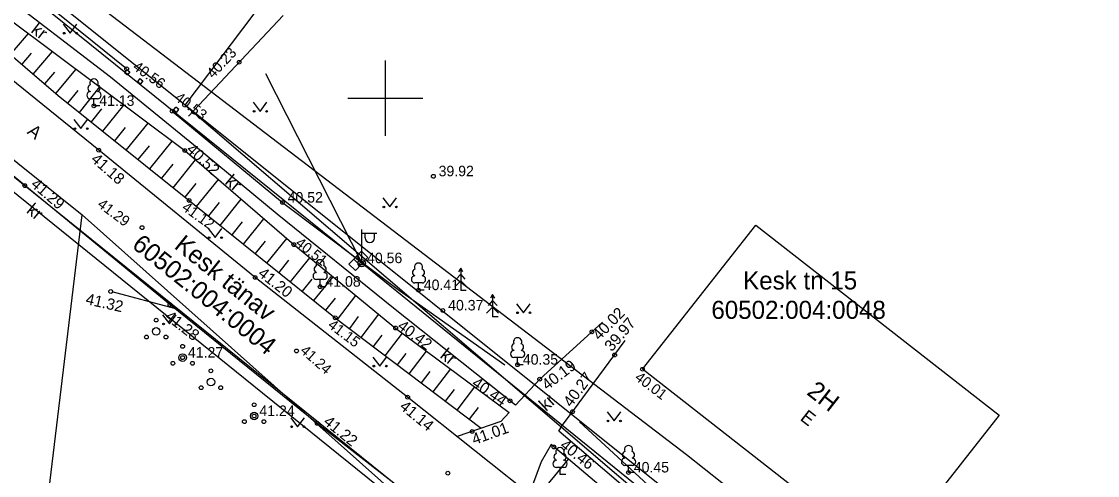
# Model space of a CAD drawing. Extents: x 641898 to 642452, y 6471715 to 6472255.
# Drawn here: x 642175.8 to 642247.4, y 6471924.9 to 6471955.1 of the extents above; entities that cross this region are included whole.
import ezdxf

# ---------------------------------------------------------------- set-up
doc = ezdxf.new("R2010")
doc.units = 0
for name, color, linetype in [('AED', 7, 'Continuous'), ('ELRAJATISMP', 7, 'Continuous'), ('HALJASTUS', 7, 'Continuous'), ('HOONE', 7, 'Continuous'), ('KORGUS-EH2000', 7, 'Continuous'), ('KTRASS', 7, 'Continuous'), ('MPOHULIIN', 7, 'Continuous'), ('PIIR', 7, 'Continuous'), ('POST', 7, 'Continuous'), ('PUU', 7, 'Continuous'), ('RELJEEF', 7, 'Continuous'), ('TEE', 7, 'Continuous'), ('VORK', 7, 'Continuous'), ('VTRASS', 7, 'Continuous')]:
    doc.layers.add(name, color=color, linetype=linetype)

msp = doc.modelspace()

# ---------------------------------------------------------------- linework, layer by layer
at = {"layer": 'AED'}
for p, q in [((642182.804, 6471951.902), (642182.661, 6471951.697)), ((642182.804, 6471951.902), (642183.009, 6471951.759)), ((642182.661, 6471951.697), (642182.866, 6471951.554)), ((642183.009, 6471951.759), (642182.866, 6471951.554)), ((642183.67, 6471951.306), (642183.514, 6471951.11)), ((642183.514, 6471951.11), (642183.71, 6471950.954)), ((642183.67, 6471951.306), (642183.866, 6471951.15)), ((642183.866, 6471951.15), (642183.71, 6471950.954)), ((642185.91, 6471949.205), (642186.066, 6471949.401)), ((642186.106, 6471949.049), (642185.91, 6471949.205)), ((642186.262, 6471949.245), (642186.066, 6471949.401)), ((642186.106, 6471949.049), (642186.262, 6471949.245))]:
    msp.add_line(p, q, dxfattribs=at)
at = {"layer": 'ELRAJATISMP'}
for p, q in [((642198.413, 6471939.812), (642197.582, 6471938.953)), ((642198.842, 6471939.397), (642198.413, 6471939.812)), ((642197.582, 6471938.953), (642198.011, 6471938.538)), ((642197.903, 6471939.285), (642198.332, 6471938.87)), ((642198.011, 6471938.538), (642198.842, 6471939.397)), ((642198.092, 6471939.48), (642198.521, 6471939.065))]:
    msp.add_line(p, q, dxfattribs=at)
at = {"layer": 'HALJASTUS'}
for p, q in [((642178.587, 6471954.924), (642179.05, 6471954.317)), ((642179.05, 6471954.317), (642179.496, 6471954.924)), ((642191.213, 6471949.724), (642191.677, 6471949.117)), ((642191.677, 6471949.117), (642192.122, 6471949.724)), ((642179.291, 6471948.578), (642179.755, 6471947.971)), ((642179.755, 6471947.971), (642180.2, 6471948.578)), ((642199.842, 6471943.362), (642200.306, 6471942.756)), ((642200.306, 6471942.756), (642200.751, 6471943.362)), ((642188.218, 6471941.32), (642188.682, 6471940.714)), ((642188.682, 6471940.714), (642189.127, 6471941.32)), ((642208.732, 6471936.318), (642209.196, 6471935.711)), ((642209.196, 6471935.711), (642209.641, 6471936.318)), ((642185.191, 6471935.578), (642185.655, 6471934.972)), ((642185.655, 6471934.972), (642186.1, 6471935.578)), ((642199.174, 6471932.77), (642199.638, 6471932.163)), ((642199.638, 6471932.163), (642200.083, 6471932.77)), ((642214.745, 6471929.119), (642215.208, 6471928.513)), ((642215.208, 6471928.513), (642215.654, 6471929.119)), ((642193.707, 6471928.732), (642194.17, 6471928.126)), ((642194.17, 6471928.126), (642194.616, 6471928.732))]:
    msp.add_line(p, q, dxfattribs=at)
for points in [[(642182.798, 6471951.948), (642174.449, 6471958.694), (642170.419, 6471961.008)], [(642186.905, 6471948.809), (642193.214, 6471955.496)], [(642185.82, 6471949.131), (642193.157, 6471943.048), (642200.95, 6471937.2), (642207.952, 6471932.258)], [(642212.922, 6471928.455), (642221.728, 6471920.311), (642230.423, 6471913.829), (642238.86, 6471907.776), (642246.219, 6471901.994)]]:
    msp.add_lwpolyline(points, dxfattribs=at)
for centre in [(642178.649, 6471954.317), (642179.478, 6471954.317), (642191.276, 6471949.117), (642192.105, 6471949.117), (642179.354, 6471947.971), (642180.183, 6471947.971), (642199.905, 6471942.756), (642200.734, 6471942.756), (642188.281, 6471940.714), (642189.109, 6471940.714), (642208.795, 6471935.711), (642209.624, 6471935.711), (642185.254, 6471934.972), (642186.082, 6471934.972), (642199.237, 6471932.163), (642200.065, 6471932.163), (642214.807, 6471928.513), (642215.636, 6471928.513), (642193.769, 6471928.126), (642194.598, 6471928.126)]:
    msp.add_circle(centre, 0.055, dxfattribs=at)
at = {"layer": 'HOONE'}
msp.add_lwpolyline([(642240.821, 6471928.89), (642233.287, 6471919.295), (642217.105, 6471931.958), (642224.638, 6471941.553), (642240.821, 6471928.89)], dxfattribs=at)
at = {"layer": 'KORGUS-EH2000'}
for centre in [(642182.798, 6471951.948), (642190.28, 6471952.386), (642180.626, 6471949.484), (642185.82, 6471949.131), (642180.941, 6471946.534), (642186.663, 6471946.509), (642203.195, 6471944.797), (642176.022, 6471944.175), (642186.952, 6471943.184), (642193.157, 6471943.048), (642183.82, 6471941.38), (642193.917, 6471940.248), (642198.436, 6471939.015), (642191.341, 6471938.065), (642195.668, 6471937.448), (642181.74, 6471937.129), (642202.208, 6471937.223), (642185.674, 6471936.257), (642196.672, 6471935.377), (642203.83, 6471935.868), (642200.688, 6471934.7), (642213.739, 6471934.446), (642194.095, 6471933.174), (642186.523, 6471932.728), (642215.25, 6471932.904), (642208.797, 6471932.26), (642217.105, 6471931.956), (642210.265, 6471931.295), (642201.484, 6471930.096), (642208.296, 6471929.851), (642191.277, 6471928.844), (642212.454, 6471929.13), (642195.477, 6471928.355), (642205.77, 6471927.816), (642211.207, 6471926.782), (642204.155, 6471925.037), (642216.174, 6471925.085)]:
    msp.add_circle(centre, 0.125, dxfattribs=at)
at = {"layer": 'KTRASS'}
msp.add_lwpolyline([(642155.58, 6471980.633), (642150.419, 6471974.152), (642145.759, 6471968.585), (642185.052, 6471936.9), (642224.346, 6471905.214)], dxfattribs=at)
at = {"layer": 'MPOHULIIN'}
for points in [[(642355.522, 6471813.313), (642331.534, 6471832.393), (642302.222, 6471855.921), (642271.629, 6471880.301), (642234.793, 6471909.555), (642198.436, 6471939.015), (642169.975, 6471961.956), (642133.076, 6471995.171), (642102.99, 6472021.089), (642074.552, 6472045.947), (642044.597, 6472041.824), (642019.939, 6472060.923), (641980.015, 6472091.706), (641945.513, 6472065.466), (641932.178, 6472056.628)], [(642192.038, 6471951.643), (642198.436, 6471939.015)]]:
    msp.add_lwpolyline(points, dxfattribs=at)
at = {"layer": 'PIIR'}
for p, q in [((642186.7, 6471949.52), (642206.053, 6471975.244)), ((642152.53, 6471964.16), (642179.85, 6471942.23)), ((642186.7, 6471949.52), (642170.2, 6471962.73)), ((642246.6, 6471901.55), (642186.7, 6471949.52)), ((642186.7, 6471949.52), (642250.92, 6471894.58)), ((642176.155, 6471911.686), (642179.85, 6471942.23)), ((642179.85, 6471942.23), (642228.06, 6471899.25))]:
    msp.add_line(p, q, dxfattribs=at)
at = {"layer": 'POST'}
for p, q in [((642198.436, 6471939.265), (642198.436, 6471941.265)), ((642198.436, 6471941.015), (642199.436, 6471941.015)), ((642198.663, 6471940.694), (642198.663, 6471941.015)), ((642199.275, 6471940.694), (642199.275, 6471941.015))]:
    msp.add_line(p, q, dxfattribs=at)
msp.add_circle((642198.436, 6471939.015), 0.25, dxfattribs=at)
msp.add_arc((642198.969, 6471940.694), 0.306, 180, 0, dxfattribs=at)
at = {"layer": 'PUU'}
for p, q in [((642180.866, 6471949.959), (642180.386, 6471949.959)), ((642180.626, 6471949.484), (642180.626, 6471949.959)), ((642181.006, 6471949.484), (642180.626, 6471949.484)), ((642205.014, 6471938.293), (642204.714, 6471937.943)), ((642205.014, 6471938.693), (642204.864, 6471938.443)), ((642205.164, 6471938.443), (642205.014, 6471938.693)), ((642205.014, 6471938.693), (642205.014, 6471937.193)), ((642205.314, 6471937.943), (642205.014, 6471938.293)), ((642195.908, 6471937.923), (642195.428, 6471937.923)), ((642195.668, 6471937.448), (642195.668, 6471937.923)), ((642202.448, 6471937.698), (642201.968, 6471937.698)), ((642202.208, 6471937.223), (642202.208, 6471937.698)), ((642205.014, 6471937.843), (642204.614, 6471937.443)), ((642205.414, 6471937.443), (642205.014, 6471937.843)), ((642196.048, 6471937.448), (642195.668, 6471937.448)), ((642202.588, 6471937.223), (642202.208, 6471937.223)), ((642205.374, 6471937.193), (642205.014, 6471937.193)), ((642207.135, 6471936.94), (642206.985, 6471936.69)), ((642207.285, 6471936.69), (642207.135, 6471936.94)), ((642207.135, 6471936.94), (642207.135, 6471935.44)), ((642207.135, 6471936.09), (642206.735, 6471935.69)), ((642207.135, 6471936.54), (642206.835, 6471936.19)), ((642207.435, 6471936.19), (642207.135, 6471936.54)), ((642207.535, 6471935.69), (642207.135, 6471936.09)), ((642207.495, 6471935.44), (642207.135, 6471935.44)), ((642209.037, 6471932.735), (642208.557, 6471932.735)), ((642208.797, 6471932.26), (642208.797, 6471932.735)), ((642209.177, 6471932.26), (642208.797, 6471932.26)), ((642211.858, 6471925.421), (642211.378, 6471925.421)), ((642211.618, 6471924.946), (642211.618, 6471925.421)), ((642216.414, 6471925.56), (642215.934, 6471925.56)), ((642216.174, 6471925.085), (642216.174, 6471925.56)), ((642211.998, 6471924.946), (642211.618, 6471924.946)), ((642216.554, 6471925.085), (642216.174, 6471925.085))]:
    msp.add_line(p, q, dxfattribs=at)
for centre, radius in [((642184.763, 6471935.225), 0.125), ((642184.763, 6471934.475), 0.25), ((642184.113, 6471934.1), 0.125), ((642185.413, 6471934.1), 0.125), ((642186.523, 6471933.478), 0.125), ((642186.523, 6471932.728), 0.25), ((642185.873, 6471932.353), 0.125), ((642187.173, 6471932.353), 0.125), ((642188.402, 6471931.852), 0.125), ((642188.402, 6471931.102), 0.25), ((642187.752, 6471930.727), 0.125), ((642189.052, 6471930.727), 0.125), ((642191.277, 6471929.594), 0.125), ((642191.277, 6471928.844), 0.25), ((642190.627, 6471928.469), 0.125), ((642191.927, 6471928.469), 0.125)]:
    msp.add_circle(centre, radius, dxfattribs=at)
for centre, radius, start, end in [((642180.626, 6471951.004), 0.277, 332.5799, 207.4201), ((642180.389, 6471950.196), 0.238, 90.0016, 269.3953), ((642180.456, 6471950.657), 0.233, 109.02174, 253.14154), ((642180.796, 6471950.657), 0.233, 286.85082, 70.98591), ((642180.863, 6471950.196), 0.238, 270.6047, 89.9984), ((642195.668, 6471938.968), 0.277, 332.5799, 207.4201), ((642202.208, 6471938.743), 0.277, 332.5799, 207.4201), ((642195.431, 6471938.16), 0.238, 90.0016, 269.3953), ((642195.498, 6471938.621), 0.233, 109.02174, 253.14154), ((642195.838, 6471938.621), 0.233, 286.85082, 70.98591), ((642195.905, 6471938.16), 0.238, 270.6047, 89.9984), ((642202.038, 6471938.396), 0.233, 109.02174, 253.14154), ((642202.378, 6471938.396), 0.233, 286.85082, 70.98591), ((642201.971, 6471937.935), 0.238, 90.0016, 269.3953), ((642202.445, 6471937.935), 0.238, 270.6047, 89.9984), ((642208.797, 6471933.78), 0.277, 332.5799, 207.4201), ((642208.56, 6471932.972), 0.238, 90.0016, 269.3953), ((642208.627, 6471933.433), 0.233, 109.02174, 253.14154), ((642208.967, 6471933.433), 0.233, 286.85082, 70.98591), ((642209.034, 6471932.972), 0.238, 270.6047, 89.9984), ((642216.174, 6471926.605), 0.277, 332.5799, 207.4201), ((642211.448, 6471926.119), 0.233, 109.02174, 253.14154), ((642211.618, 6471926.466), 0.277, 332.5799, 207.4201), ((642211.788, 6471926.119), 0.233, 286.85082, 70.98591), ((642216.004, 6471926.258), 0.233, 109.02174, 253.14154), ((642216.344, 6471926.258), 0.233, 286.85082, 70.98591), ((642211.381, 6471925.658), 0.238, 90.0016, 269.3953), ((642211.855, 6471925.658), 0.238, 270.6047, 89.9984), ((642215.937, 6471925.797), 0.238, 90.0016, 269.3953), ((642216.411, 6471925.797), 0.238, 270.6047, 89.9984)]:
    msp.add_arc(centre, radius, start, end, dxfattribs=at)
at = {"layer": 'RELJEEF'}
for p, q in [((642175.064, 6471952.906), (642176.266, 6471954.306)), ((642176.445, 6471952.98), (642175.823, 6471952.255)), ((642176.582, 6471951.604), (642177.869, 6471953.103)), ((642178.099, 6471950.301), (642179.451, 6471951.918)), ((642178.006, 6471951.727), (642177.341, 6471950.952)), ((642179.549, 6471950.504), (642178.875, 6471949.67)), ((642179.655, 6471949.044), (642181.018, 6471950.742)), ((642181.127, 6471949.28), (642180.434, 6471948.418)), ((642181.214, 6471947.791), (642182.619, 6471949.541)), ((642182.774, 6471946.539), (642184.22, 6471948.341)), ((642182.707, 6471948.053), (642181.994, 6471947.165)), ((642184.287, 6471946.827), (642183.553, 6471945.913)), ((642184.333, 6471945.287), (642185.821, 6471947.14)), ((642185.867, 6471945.6), (642185.113, 6471944.661)), ((642185.893, 6471944.035), (642187.381, 6471945.889)), ((642187.406, 6471944.322), (642186.672, 6471943.409)), ((642187.452, 6471942.782), (642188.897, 6471944.581)), ((642189.011, 6471941.53), (642190.412, 6471943.274)), ((642188.943, 6471943.042), (642188.232, 6471942.156)), ((642190.571, 6471940.278), (642191.927, 6471941.966)), ((642190.48, 6471941.762), (642189.791, 6471940.904)), ((642192.017, 6471940.482), (642191.35, 6471939.651)), ((642192.13, 6471939.025), (642193.442, 6471940.658)), ((642193.557, 6471939.205), (642192.91, 6471938.399)), ((642193.689, 6471937.773), (642194.979, 6471939.378)), ((642195.11, 6471937.945), (642194.469, 6471937.147)), ((642195.248, 6471936.52), (642196.526, 6471938.11)), ((642196.811, 6471935.272), (642198.047, 6471936.864)), ((642196.662, 6471936.687), (642196.028, 6471935.894)), ((642198.205, 6471935.457), (642197.608, 6471934.668)), ((642198.405, 6471934.064), (642199.576, 6471935.611)), ((642199.776, 6471934.219), (642199.202, 6471933.461)), ((642200, 6471932.857), (642201.14, 6471934.363)), ((642201.37, 6471933.01), (642200.797, 6471932.253)), ((642201.594, 6471931.65), (642202.745, 6471933.169)), ((642202.969, 6471931.809), (642202.391, 6471931.046)), ((642203.189, 6471930.442), (642204.35, 6471931.975)), ((642204.569, 6471930.608), (642203.986, 6471929.838)), ((642204.783, 6471929.235), (642205.954, 6471930.782)), ((642206.168, 6471929.408), (642205.58, 6471928.631)), ((642210.769, 6471924.245), (642212.172, 6471925.968))]:
    msp.add_line(p, q, dxfattribs=at)
msp.add_lwpolyline([(642153.761, 6471970.265), (642161.15, 6471964.505), (642169.596, 6471957.601), (642178.247, 6471950.174), (642186.952, 6471943.184), (642196.672, 6471935.377), (642206.377, 6471928.027)], dxfattribs=at)
at = {"layer": 'TEE'}
for points in [[(642248.038, 6471894.359), (642244.819, 6471896.591), (642243.421, 6471898.287), (642241.287, 6471898.567), (642230.451, 6471907.231), (642220.045, 6471915.264), (642210.382, 6471923.001), (642201.484, 6471930.096), (642191.341, 6471938.065), (642180.941, 6471946.534), (642171.256, 6471954.365), (642153.477, 6471969.856), (642154.958, 6471971.99), (642153.566, 6471973.386), (642153.495, 6471974.667), (642149.137, 6471978.135), (642148.146, 6471977.701), (642140.89, 6471983.962), (642132.244, 6471991.056), (642124.462, 6471997.136), (642114.29, 6472005.762), (642111.738, 6472008.121), (642108.086, 6472011.066)], [(642253.944, 6471882.162), (642243.566, 6471890.342), (642234.582, 6471897.491), (642228.739, 6471901.846), (642227.951, 6471901.93), (642224.85, 6471904.256), (642224.883, 6471905.449), (642215.573, 6471912.361), (642205.766, 6471920.313), (642195.477, 6471928.355), (642185.674, 6471936.257), (642176.022, 6471944.175), (642167.777, 6471951.014), (642158.111, 6471959.24), (642148.973, 6471966.102), (642138.436, 6471974.464), (642128.627, 6471982.536), (642127.755, 6471983.25), (642118.56, 6471990.787)], [(642214.441, 6471935.082), (642210.265, 6471931.295), (642208.667, 6471929.555), (642200.55, 6471936.024), (642192.814, 6471942.275), (642187.251, 6471946.896), (642181.726, 6471951.396), (642174.008, 6471957.307), (642163.973, 6471965.281), (642157.225, 6471970.564), (642154.958, 6471971.99)], [(642154.355, 6471971.122), (642157.028, 6471969.169), (642169.227, 6471959.585), (642186.663, 6471946.509), (642193.917, 6471940.248), (642200.688, 6471934.7), (642208.235, 6471929.084), (642207.681, 6471928.481), (642204.777, 6471927.47)], [(642185.982, 6471936.009), (642181.845, 6471937.101)], [(642250.614, 6471903.45), (642247.126, 6471899.514), (642236.062, 6471907.65), (642226.459, 6471915.651), (642218.711, 6471921.682), (642211.545, 6471927.832), (642211.763, 6471928.205), (642212.454, 6471929.13), (642215.961, 6471933.863)], [(642243.557, 6471898.122), (642245.655, 6471898.552), (642244.803, 6471899.853), (642237.623, 6471905.411), (642229.091, 6471912.308), (642219.24, 6471920.009), (642211.023, 6471926.937), (642210.355, 6471925.793), (642209.576, 6471923.644)]]:
    msp.add_lwpolyline(points, dxfattribs=at)
at = {"layer": 'VORK'}
for p, q in [((642200, 6471952.5), (642200, 6471947.5)), ((642197.5, 6471950), (642202.5, 6471950))]:
    msp.add_line(p, q, dxfattribs=at)
at = {"layer": 'VTRASS'}
for points in [[(642256.057, 6471879.253), (642241.436, 6471890.95), (642226.363, 6471903.005), (642214.466, 6471912.082), (642191.253, 6471930.836), (642159.201, 6471956.73), (642153.648, 6471961.39), (642148.095, 6471966.051), (642145.394, 6471966.921), (642144.516, 6471967.495), (642143.631, 6471968.002), (642136.85, 6471974.118), (642135.798, 6471974.98), (642131.146, 6471978.791)], [(642261.241, 6471893.85), (642226.798, 6471920.874), (642223.555, 6471923.471), (642220.019, 6471926.258), (642175.39, 6471960.391)]]:
    msp.add_lwpolyline(points, dxfattribs=at)

# ---------------------------------------------------------------- texts
at = {"layer": 'HOONE'}
for s, height, p in [('2H', 1.2, (642227.962, 6471930.324)), ('E', 0.9, (642227.529, 6471928.615))]:
    msp.add_text(s, height=height, rotation=321.955, dxfattribs=at).set_placement(p)
at = {"layer": 'KORGUS-EH2000'}
for s, height, rotation, p in [('40.23', 0.7, 46.65376, (642188.553, 6471951.26)), ('40.56', 0.7, 324.19469, (642183.148, 6471951.948)), ('40.53', 0.7, 322.88504, (642185.935, 6471949.903)), ('40.52', 0.75, 316.69775, (642186.726, 6471946.509)), ('41.18', 0.75, 318.76113, (642180.368, 6471945.846)), ('41.29', 0.75, 319.21115, (642176.372, 6471944.175)), ('41.29', 0.7, 323.23602, (642180.798, 6471942.813)), ('41.12', 0.7, 324.21699, (642186.414, 6471942.597)), ('40.51', 0.7, 321.62852, (642193.965, 6471940.248)), ('41.20', 0.75, 321.77224, (642191.478, 6471938.22)), ('41.32', 0.75, 347.16376, (642180.027, 6471936.3)), ('41.28', 0.75, 322.16057, (642185.284, 6471935.339)), ('40.02', 0.75, 45.64097, (642214.233, 6471933.832)), ('39.97', 0.75, 49.23926, (642215.063, 6471933.086)), ('41.15', 0.7, 322.83674, (642196.123, 6471934.785)), ('40.42', 0.75, 323.19936, (642200.746, 6471934.7)), ('41.24', 0.7, 318.47551, (642194.283, 6471933.116)), ('40.19', 0.75, 37.60721, (642210.766, 6471930.523)), ('40.27', 0.75, 53.35085, (642212.363, 6471929.385)), ('40.44', 0.75, 325.60361, (642205.693, 6471930.875)), ('40.01', 0.7, 322.86657, (642216.535, 6471931.294)), ('41.14', 0.75, 320.49205, (642200.894, 6471929.374)), ('41.22', 0.75, 320.87537, (642195.827, 6471928.355)), ('41.01', 0.75, 19.62298, (642205.911, 6471926.916)), ('40.46', 0.75, 321.78458, (642211.557, 6471926.782))]:
    msp.add_text(s, height=height, rotation=rotation, dxfattribs=at).set_placement(p)
for s, p in [('41.13', (642180.976, 6471949.484)), ('39.92', (642203.545, 6471944.797)), ('40.52', (642193.507, 6471943.048)), ('40.56', (642198.786, 6471939.015)), ('41.08', (642196.018, 6471937.448)), ('40.41', (642202.558, 6471937.223)), ('40.37', (642204.18, 6471935.868)), ('41.27', (642186.873, 6471932.728)), ('40.35', (642209.147, 6471932.26)), ('41.24', (642191.627, 6471928.844)), ('40.45', (642216.524, 6471925.085))]:
    msp.add_text(s, height=0.7, dxfattribs=at).set_placement(p)
at = {"layer": 'PIIR'}
for s, p in [('60502:004:0004', (642183.081, 6471940.096)), ('Kesk tänav', (642185.895, 6471940.053))]:
    msp.add_text(s, height=1.2, rotation=321.23622, dxfattribs=at).set_placement(p)
for s, p in [('Kesk tn 15', (642223.796, 6471937.264)), ('60502:004:0048', (642221.682, 6471935.31))]:
    msp.add_text(s, height=1.2, dxfattribs=at).set_placement(p)
at = {"layer": 'TEE'}
for s, rotation, p in [('kr', 322.55251, (642176.378, 6471954.417)), ('A', 321.04204, (642176.129, 6471947.679)), ('kr', 320.28471, (642189.278, 6471944.337)), ('kr', 320.63632, (642176.076, 6471942.419)), ('kr', 321.4477, (642203.58, 6471932.768)), ('kr', 42.20877, (642210.689, 6471929.116))]:
    msp.add_text(s, height=0.85, rotation=rotation, dxfattribs=at).set_placement(p)

doc.saveas('drawing.dxf')
